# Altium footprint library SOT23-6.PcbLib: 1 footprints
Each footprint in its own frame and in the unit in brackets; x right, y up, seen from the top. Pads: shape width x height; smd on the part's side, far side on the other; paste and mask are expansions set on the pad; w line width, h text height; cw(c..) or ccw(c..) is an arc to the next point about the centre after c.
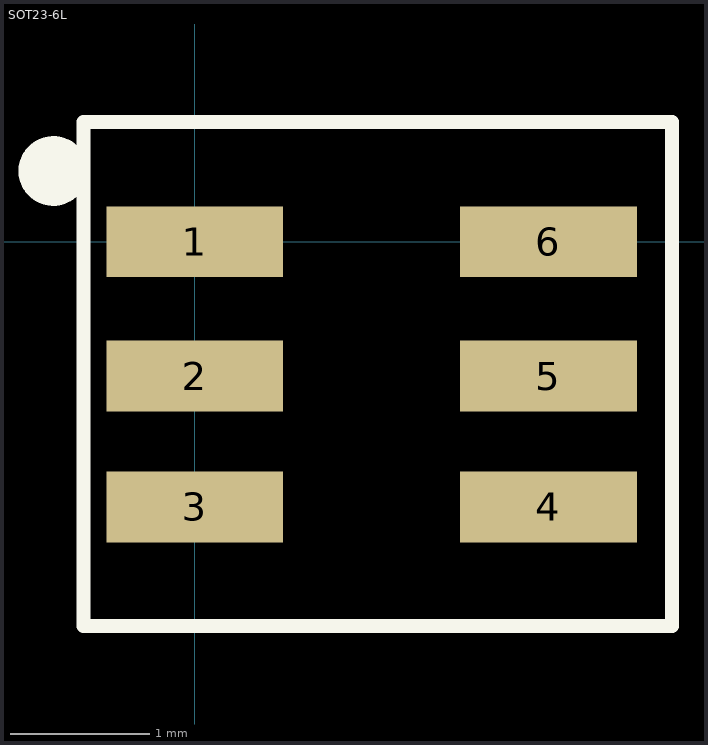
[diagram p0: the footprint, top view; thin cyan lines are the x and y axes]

## SOT23-6L [mil]
pads (6):
  rect 50x20 smd: 1(0,0) 2(0,-38) 3(0,-75) 4(100,-75) 5(100,-37.99) 6(100,0)
Top Overlay:
  circle w9.84: c-40,20 r4.92
  lines w3.94: -31.5,-108.66 135,-108.66 135,-64.02 135,7.24 135,33.86 -31.5,33.86 -31.5,-108.66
